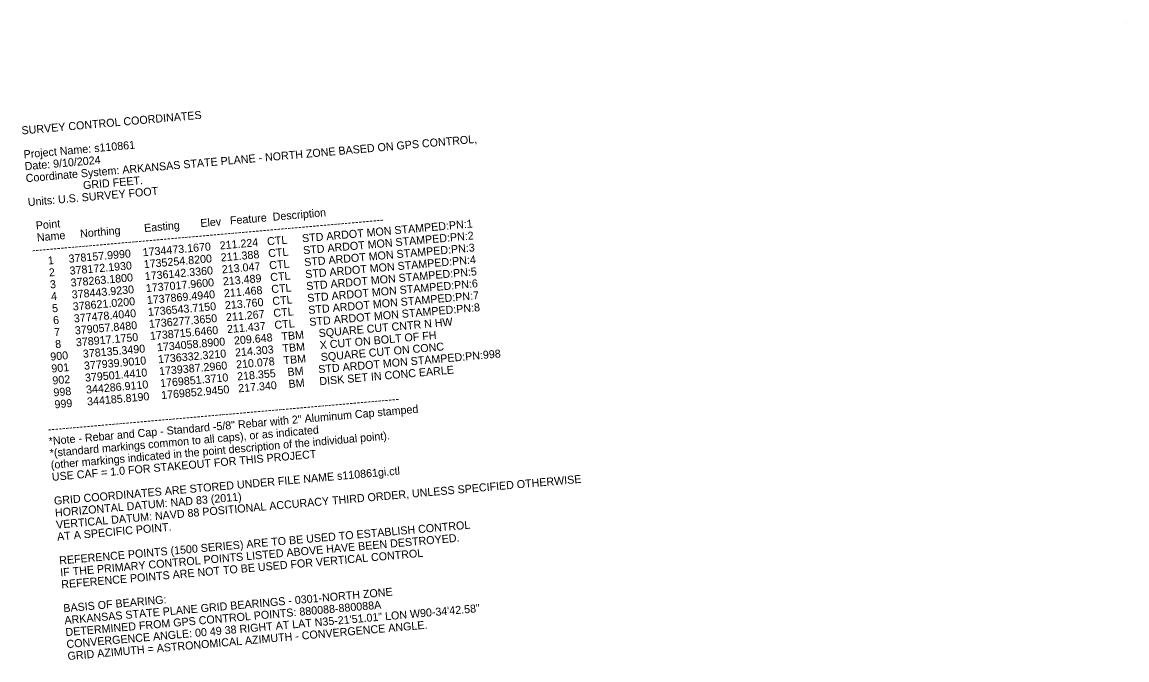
# Model space of a CAD drawing. Extents: x 1734811 to 1736288, y 377764 to 378763.
# Drawn here: x 1734811 to 1735501, y 378245 to 378643 of the extents above; entities that cross this region are included whole.
import ezdxf

# ---------------------------------------------------------------- set-up
doc = ezdxf.new("R2010")
doc.units = 0
doc.layers.add('Default', color=7, linetype='Continuous')
doc.layers.add('Level 8', color=7, linetype='Continuous')

msp = doc.modelspace()

# ---------------------------------------------------------------- linework, layer by layer
at = {"layer": 'Level 8'}
msp.add_line((1735501.13, 378643.47), (1735501.13, 378643.47), dxfattribs=at)

# ---------------------------------------------------------------- texts
at = {"layer": 'Default'}
for s, p in [('SURVEY CONTROL COORDINATES ', (1734810.53, 378573.18)), ('Project Name: s110861 ', (1734811.84, 378558.24)), ('Coordinate System: ARKANSAS STATE PLANE - NORTH ZONE BASED ON GPS CONTROL, ', (1734813.15, 378543.3)), ('Date: 9/10/2024 ', (1734812.49, 378550.77)), ('                   GRID FEET. ', (1734813.8, 378535.82)), ('Units: U.S. SURVEY FOOT ', (1734814.46, 378528.35)), ('  Name     Northing        Easting       Elev   Feature  Description ', (1734816.42, 378505.94)), ('--------------------------------------------------------------------------------------------------- ', (1734817.07, 378498.47)), ('  Point ', (1734815.76, 378513.41)), ('     1     378157.9990    1734473.1670   211.224   CTL     STD ARDOT MON STAMPED:PN:1 ', (1734817.72, 378491)), ('     2     378172.1930    1735254.8200   211.388   CTL     STD ARDOT MON STAMPED:PN:2 ', (1734818.38, 378483.52)), ('     3     378263.1800    1736142.3360   213.047   CTL     STD ARDOT MON STAMPED:PN:3 ', (1734819.03, 378476.05)), ('     4     378443.9230    1737017.9600   213.489   CTL     STD ARDOT MON STAMPED:PN:4 ', (1734819.69, 378468.58)), ('     5     378621.0200    1737869.4940   211.468   CTL     STD ARDOT MON STAMPED:PN:5 ', (1734820.34, 378461.11)), ('     6     377478.4040    1736543.7150   213.760   CTL     STD ARDOT MON STAMPED:PN:6 ', (1734820.99, 378453.64)), ('     7     379057.8480    1736277.3650   211.267   CTL     STD ARDOT MON STAMPED:PN:7 ', (1734821.65, 378446.17)), ('     8     378917.1750    1738715.6460   211.437   CTL     STD ARDOT MON STAMPED:PN:8 ', (1734822.3, 378438.7)), ('   900     378135.3490    1734058.8900   209.648   TBM     SQUARE CUT CNTR N HW ', (1734822.95, 378431.22)), ('   901     377939.9010    1736332.3210   214.303   TBM     X CUT ON BOLT OF FH ', (1734823.61, 378423.75)), ('   902     379501.4410    1739387.2960   210.078   TBM     SQUARE CUT ON CONC ', (1734824.26, 378416.28)), ('   998     344286.9110    1769851.3710   218.355    BM     STD ARDOT MON STAMPED:PN:998 ', (1734824.91, 378408.81)), ('   999     344185.8190    1769852.9450   217.340    BM     DISK SET IN CONC EARLE ', (1734825.57, 378401.34)), ('--------------------------------------------------------------------------------------------------- ', (1734826.88, 378386.4)), ('*Note - Rebar and Cap - Standard -5/8" Rebar with 2" Aluminum Cap stamped ', (1734827.53, 378378.92)), ('*(standard markings common to all caps), or as indicated ', (1734828.18, 378371.45)), ('(other markings indicated in the point description of the individual point).  ', (1734828.84, 378363.98)), ('USE CAF = 1.0 FOR STAKEOUT FOR THIS PROJECT ', (1734829.49, 378356.51)), ('GRID COORDINATES ARE STORED UNDER FILE NAME s110861gi.ctl  ', (1734830.8, 378341.57)), ('VERTICAL DATUM: NAVD 88 POSITIONAL ACCURACY THIRD ORDER, UNLESS SPECIFIED OTHERWISE  ', (1734832.1, 378326.62)), ('HORIZONTAL DATUM: NAD 83 (2011) ', (1734831.45, 378334.09)), ('AT A SPECIFIC POINT. ', (1734832.76, 378319.15)), ('REFERENCE POINTS (1500 SERIES) ARE TO BE USED TO ESTABLISH CONTROL ', (1734834.07, 378304.21)), ('IF THE PRIMARY CONTROL POINTS LISTED ABOVE HAVE BEEN DESTROYED. ', (1734834.72, 378296.74)), ('REFERENCE POINTS ARE NOT TO BE USED FOR VERTICAL CONTROL ', (1734835.37, 378289.27)), ('BASIS OF BEARING: ', (1734836.68, 378274.32)), ('ARKANSAS STATE PLANE GRID BEARINGS - 0301-NORTH ZONE', (1734837.33, 378266.85)), ('DETERMINED FROM GPS CONTROL POINTS: 880088-880088A ', (1734837.99, 378259.38)), ('CONVERGENCE ANGLE: 00 49 38 RIGHT AT LAT N35-21\'51.01" LON W90-34\'42.58"', (1734838.64, 378251.91)), ('GRID AZIMUTH = ASTRONOMICAL AZIMUTH - CONVERGENCE ANGLE. ', (1734839.3, 378244.44))]:
    msp.add_text(s, height=5, rotation=5, dxfattribs=at).set_placement(p)

doc.saveas('drawing.dxf')
